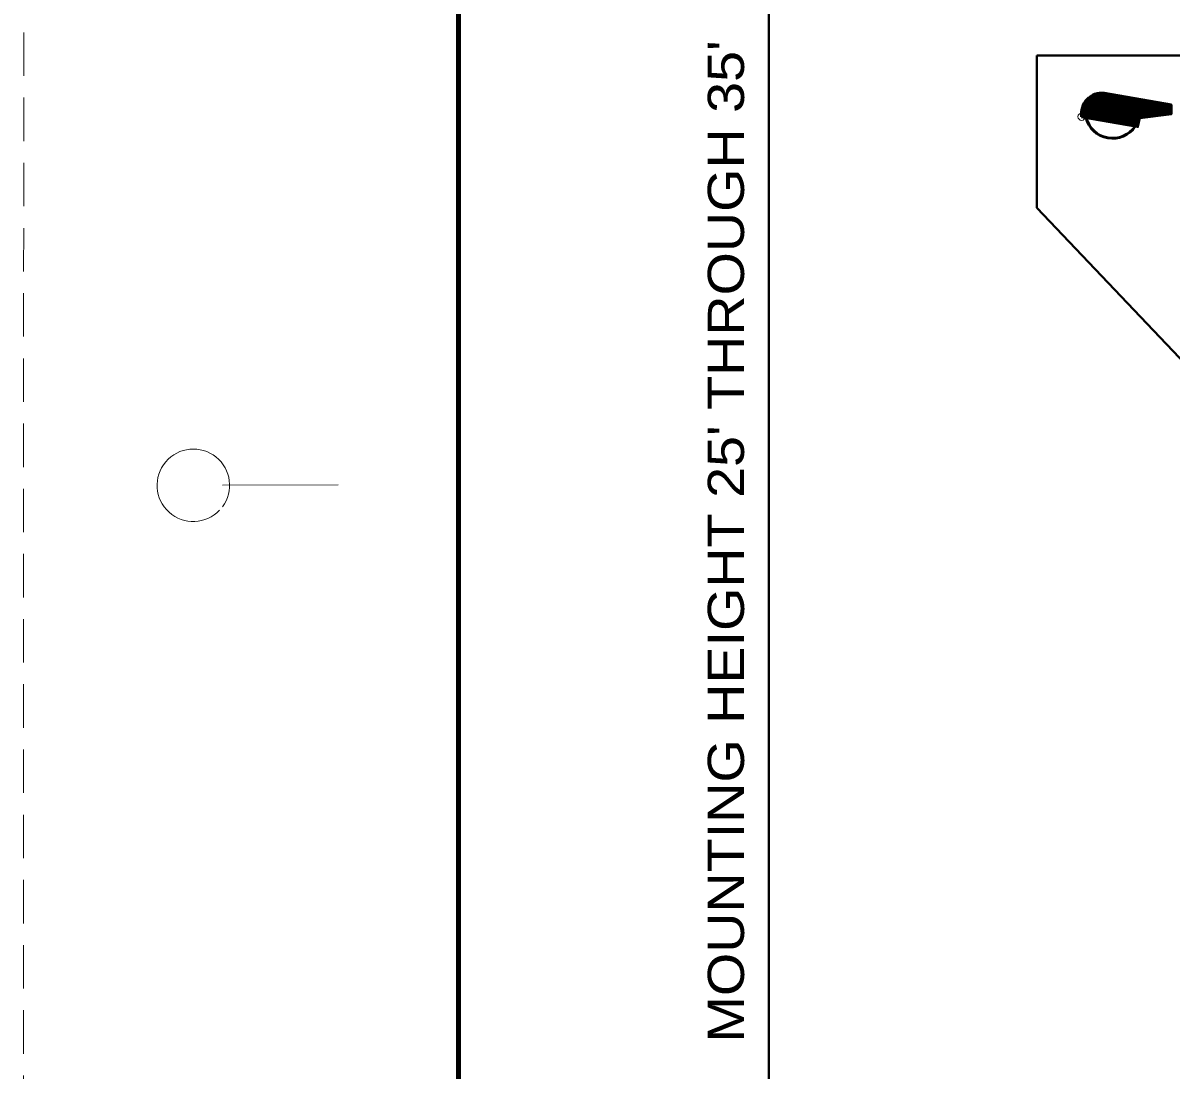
# Model space of a CAD drawing. Extents: x -1 to 679, y 1 to 441.
# Drawn here: x -0.7 to 78.6, y 301.7 to 374 of the extents above; entities that cross this region are included whole.
import ezdxf

# ---------------------------------------------------------------- set-up
doc = ezdxf.new("R2010")
doc.units = 0
doc.header["$PDMODE"] = 32
doc.header["$PDSIZE"] = 0.5
doc.linetypes.add('MEDIUM_DASHED', pattern=[4.5, 3, -1.5])
doc.layers.add('1', color=7, linetype='Continuous', lineweight=13)
doc.layers.add('61', color=7, linetype='Continuous', lineweight=35)

msp = doc.modelspace()

# ---------------------------------------------------------------- linework, layer by layer
at = {"layer": '1', "linetype": 'MEDIUM_DASHED'}
msp.add_line((-0.608, 440.866), (-0.668, 0.826), dxfattribs=at)
at = {"layer": '1', "lineweight": 40}
for p, q in [((50.801, 409.017), (50.801, 261.017)), ((69.301, 371.767), (69.301, 361.267)), ((126.301, 371.767), (69.301, 371.767)), ((69.301, 361.267), (87.801, 341.767))]:
    msp.add_line(p, q, dxfattribs=at)
at = {"layer": '1', "lineweight": 53}
for p, q in [((72.408, 368.076), (73.478, 369.147)), ((72.42, 368.133), (73.419, 369.132)), ((72.442, 368.199), (73.355, 369.112)), ((72.464, 368.265), (73.288, 369.09)), ((72.498, 368.343), (73.211, 369.056)), ((72.537, 368.427), (73.124, 369.013)), ((72.601, 368.535), (73.017, 368.951)), ((72.621, 368.246), (73.533, 369.158)), ((72.666, 368.246), (73.588, 369.169)), ((72.71, 368.246), (73.637, 369.173)), ((72.754, 368.246), (73.686, 369.178)), ((72.798, 368.246), (73.735, 369.183)), ((72.798, 368.776), (72.799, 368.777)), ((72.842, 368.246), (73.779, 369.183)), ((72.886, 368.246), (73.823, 369.182)), ((72.931, 368.246), (73.867, 369.182)), ((72.975, 368.246), (73.909, 369.18)), ((73.019, 368.246), (73.949, 369.176)), ((73.063, 368.246), (73.986, 369.169)), ((73.108, 368.246), (74.024, 369.162)), ((73.152, 368.246), (74.062, 369.156)), ((73.196, 368.246), (74.099, 369.149)), ((73.24, 368.246), (74.137, 369.142)), ((73.284, 368.246), (74.174, 369.136)), ((73.328, 368.246), (74.212, 369.129)), ((73.373, 368.246), (74.249, 369.123)), ((73.417, 368.246), (74.287, 369.116)), ((73.461, 368.246), (74.325, 369.109)), ((73.505, 368.246), (74.362, 369.103)), ((73.549, 368.246), (74.4, 369.096)), ((73.594, 368.246), (74.437, 369.09)), ((73.638, 368.246), (74.475, 369.083)), ((73.682, 368.246), (74.512, 369.076)), ((73.726, 368.246), (74.55, 369.07)), ((73.77, 368.246), (74.588, 369.063)), ((73.815, 368.246), (74.625, 369.056)), ((73.859, 368.246), (74.663, 369.05)), ((73.903, 368.246), (74.7, 369.043)), ((73.947, 368.246), (74.738, 369.036)), ((73.991, 368.246), (74.775, 369.03)), ((74.036, 368.246), (74.813, 369.023)), ((74.08, 368.246), (74.851, 369.017)), ((74.124, 368.246), (74.888, 369.01)), ((74.168, 368.246), (74.926, 369.003)), ((74.212, 368.246), (74.963, 368.997)), ((74.257, 368.246), (75.001, 368.99)), ((74.301, 368.246), (75.038, 368.983)), ((74.345, 368.246), (75.076, 368.977)), ((74.389, 368.246), (75.114, 368.97)), ((74.433, 368.246), (75.151, 368.964)), ((74.477, 368.246), (75.189, 368.957)), ((74.522, 368.246), (75.226, 368.95)), ((74.566, 368.246), (75.264, 368.944)), ((74.61, 368.246), (75.301, 368.937)), ((74.654, 368.246), (75.339, 368.93)), ((74.698, 368.246), (75.377, 368.924)), ((74.743, 368.246), (75.414, 368.917)), ((74.787, 368.246), (75.452, 368.911)), ((74.831, 368.246), (75.489, 368.904)), ((74.875, 368.246), (75.527, 368.897)), ((74.919, 368.246), (75.564, 368.891)), ((74.964, 368.246), (75.602, 368.884)), ((75.008, 368.246), (75.639, 368.878)), ((75.052, 368.246), (75.677, 368.871)), ((75.096, 368.246), (75.715, 368.864)), ((75.14, 368.246), (75.752, 368.858)), ((75.185, 368.246), (75.79, 368.851)), ((75.229, 368.246), (75.827, 368.844)), ((75.273, 368.246), (75.865, 368.838)), ((75.317, 368.246), (75.903, 368.831)), ((75.361, 368.246), (75.94, 368.825)), ((75.406, 368.246), (75.978, 368.818)), ((75.45, 368.246), (76.015, 368.811)), ((75.494, 368.246), (76.053, 368.805)), ((75.538, 368.246), (76.09, 368.798)), ((75.582, 368.246), (76.128, 368.791)), ((75.627, 368.246), (76.166, 368.785)), ((75.671, 368.246), (76.203, 368.778)), ((75.715, 368.246), (76.241, 368.772)), ((75.759, 368.246), (76.278, 368.765)), ((75.803, 368.246), (76.316, 368.758)), ((75.847, 368.246), (76.353, 368.752)), ((75.892, 368.246), (76.391, 368.745)), ((75.936, 368.246), (76.428, 368.738)), ((75.98, 368.246), (76.466, 368.732)), ((76.024, 368.246), (76.504, 368.725)), ((76.069, 368.246), (76.541, 368.719)), ((76.113, 368.246), (76.579, 368.712)), ((76.157, 368.246), (76.616, 368.705)), ((76.201, 368.246), (76.654, 368.699)), ((76.245, 368.246), (76.691, 368.692)), ((76.29, 368.246), (76.729, 368.685)), ((76.334, 368.246), (76.767, 368.679)), ((76.378, 368.246), (76.804, 368.672)), ((76.422, 368.246), (76.842, 368.666)), ((76.466, 368.246), (76.879, 368.659)), ((76.51, 368.246), (76.917, 368.652)), ((76.555, 368.246), (76.954, 368.646)), ((76.599, 368.246), (76.992, 368.639)), ((76.643, 368.246), (77.03, 368.632)), ((76.687, 368.246), (77.067, 368.626)), ((76.731, 368.246), (77.105, 368.619)), ((76.776, 368.246), (77.142, 368.613)), ((76.82, 368.246), (77.18, 368.606)), ((76.864, 368.246), (77.217, 368.599)), ((76.908, 368.246), (77.255, 368.593)), ((76.952, 368.246), (77.293, 368.586)), ((76.997, 368.246), (77.33, 368.579)), ((77.041, 368.246), (77.368, 368.573)), ((77.085, 368.246), (77.405, 368.566)), ((77.129, 368.246), (77.443, 368.56)), ((77.173, 368.246), (77.48, 368.553)), ((77.218, 368.246), (77.518, 368.546)), ((77.262, 368.246), (77.556, 368.54)), ((77.306, 368.246), (77.593, 368.533)), ((77.35, 368.246), (77.631, 368.526)), ((77.394, 368.246), (77.668, 368.52)), ((77.439, 368.246), (77.706, 368.513)), ((77.483, 368.246), (77.743, 368.506)), ((77.527, 368.246), (77.781, 368.5)), ((77.571, 368.246), (77.819, 368.493)), ((77.615, 368.246), (77.856, 368.487)), ((77.659, 368.246), (77.894, 368.48)), ((77.704, 368.246), (77.931, 368.473)), ((77.748, 368.246), (77.969, 368.467)), ((77.792, 368.246), (78.006, 368.46)), ((77.836, 368.246), (78.044, 368.453)), ((77.88, 368.246), (78.082, 368.447)), ((77.925, 368.246), (78.119, 368.44)), ((77.969, 368.246), (78.157, 368.434)), ((78.013, 368.246), (78.194, 368.427)), ((78.057, 368.246), (78.232, 368.42)), ((78.102, 368.246), (78.269, 368.414)), ((78.146, 368.246), (78.307, 368.407)), ((78.19, 368.246), (78.344, 368.401)), ((72.371, 367.775), (72.764, 368.168)), ((72.371, 367.73), (72.808, 368.168)), ((72.371, 367.686), (72.853, 368.168)), ((72.372, 367.819), (72.72, 368.168)), ((72.374, 367.866), (72.676, 368.168)), ((72.375, 367.646), (72.897, 368.168)), ((72.379, 367.606), (72.941, 368.168)), ((72.38, 367.916), (72.632, 368.168)), ((72.383, 367.565), (72.985, 368.168)), ((72.386, 367.966), (72.612, 368.192)), ((72.395, 368.019), (72.612, 368.237)), ((72.406, 367.544), (73.029, 368.168)), ((72.443, 367.537), (73.074, 368.168)), ((72.481, 367.531), (73.118, 368.168)), ((72.518, 367.524), (73.162, 368.168)), ((72.556, 367.517), (73.206, 368.168)), ((72.593, 367.511), (73.25, 368.168)), ((72.631, 367.504), (73.294, 368.168)), ((72.668, 367.498), (73.339, 368.168)), ((72.706, 367.491), (73.383, 368.168)), ((72.744, 367.484), (73.427, 368.168)), ((72.781, 367.478), (73.471, 368.168)), ((72.819, 367.471), (73.516, 368.168)), ((72.856, 367.464), (73.56, 368.168)), ((72.894, 367.458), (73.604, 368.168)), ((72.931, 367.451), (73.648, 368.168)), ((72.969, 367.444), (73.692, 368.168)), ((73.007, 367.438), (73.736, 368.168)), ((73.044, 367.431), (73.781, 368.168)), ((73.082, 367.425), (73.825, 368.168)), ((73.119, 367.418), (73.869, 368.168)), ((73.157, 367.411), (73.913, 368.168)), ((73.194, 367.405), (73.957, 368.168)), ((73.232, 367.398), (74.002, 368.168)), ((73.27, 367.391), (74.046, 368.168)), ((73.307, 367.385), (74.09, 368.168)), ((73.345, 367.378), (74.134, 368.168)), ((73.382, 367.372), (74.178, 368.168)), ((73.42, 367.365), (74.223, 368.168)), ((73.457, 367.358), (74.267, 368.168)), ((73.495, 367.352), (74.311, 368.168)), ((73.533, 367.345), (74.355, 368.168)), ((73.57, 367.339), (74.399, 368.168)), ((73.608, 367.332), (74.444, 368.168)), ((73.645, 367.325), (74.488, 368.168)), ((73.683, 367.319), (74.532, 368.168)), ((73.72, 367.312), (74.576, 368.168)), ((73.758, 367.305), (74.62, 368.168)), ((73.796, 367.299), (74.665, 368.168)), ((73.833, 367.292), (74.709, 368.168)), ((73.871, 367.286), (74.753, 368.168)), ((73.908, 367.279), (74.797, 368.168)), ((73.946, 367.272), (74.841, 368.168)), ((73.983, 367.266), (74.886, 368.168)), ((74.021, 367.259), (74.93, 368.168)), ((74.059, 367.252), (74.974, 368.168)), ((74.096, 367.246), (75.018, 368.168)), ((74.134, 367.239), (75.062, 368.168)), ((74.171, 367.233), (75.106, 368.168)), ((74.209, 367.226), (75.151, 368.168)), ((74.246, 367.219), (75.195, 368.168)), ((74.284, 367.213), (75.239, 368.168)), ((74.322, 367.206), (75.283, 368.168)), ((74.359, 367.199), (75.328, 368.168)), ((74.397, 367.193), (75.372, 368.168)), ((74.434, 367.186), (75.416, 368.168)), ((74.472, 367.179), (75.46, 368.168)), ((74.509, 367.173), (75.504, 368.168)), ((74.547, 367.166), (75.549, 368.168)), ((74.584, 367.16), (75.593, 368.168)), ((74.622, 367.153), (75.637, 368.168)), ((74.66, 367.146), (75.681, 368.168)), ((74.697, 367.14), (75.725, 368.168)), ((74.735, 367.133), (75.769, 368.168)), ((74.772, 367.126), (75.814, 368.168)), ((74.81, 367.12), (75.858, 368.168)), ((74.847, 367.113), (75.902, 368.168)), ((74.885, 367.107), (75.946, 368.168)), ((74.923, 367.1), (75.99, 368.168)), ((74.96, 367.093), (76.035, 368.168)), ((74.998, 367.087), (76.079, 368.168)), ((75.035, 367.08), (76.123, 368.168)), ((75.073, 367.073), (76.167, 368.168)), ((75.11, 367.067), (76.211, 368.168)), ((75.148, 367.06), (76.256, 368.168)), ((75.186, 367.054), (76.3, 368.168)), ((75.223, 367.047), (76.344, 368.168)), ((75.261, 367.04), (76.388, 368.168)), ((75.298, 367.034), (76.432, 368.168)), ((75.336, 367.027), (76.477, 368.168)), ((75.373, 367.02), (76.521, 368.168)), ((75.411, 367.014), (76.565, 368.168)), ((75.449, 367.007), (76.609, 368.168)), ((75.486, 367.001), (76.653, 368.168)), ((75.524, 366.994), (76.697, 368.168)), ((75.561, 366.987), (76.742, 368.168)), ((75.599, 366.981), (76.786, 368.168)), ((75.636, 366.974), (76.83, 368.168)), ((75.674, 366.967), (76.874, 368.168)), ((75.712, 366.961), (76.918, 368.168)), ((75.749, 366.954), (76.963, 368.168)), ((75.787, 366.948), (77.007, 368.168)), ((75.824, 366.941), (77.051, 368.168)), ((76.401, 367.473), (77.095, 368.168)), ((76.451, 367.479), (77.139, 368.168)), ((76.501, 367.486), (77.184, 368.168)), ((76.552, 367.492), (77.228, 368.168)), ((76.602, 367.498), (77.272, 368.168)), ((76.653, 367.504), (77.316, 368.168)), ((76.703, 367.51), (77.36, 368.168)), ((76.754, 367.517), (77.405, 368.168)), ((76.804, 367.523), (77.449, 368.168)), ((76.854, 367.529), (77.493, 368.168)), ((76.905, 367.535), (77.537, 368.168)), ((76.955, 367.541), (77.581, 368.168)), ((77.005, 367.548), (77.626, 368.168)), ((77.056, 367.554), (77.67, 368.168)), ((77.106, 367.56), (77.714, 368.168)), ((77.156, 367.566), (77.758, 368.168)), ((77.207, 367.572), (77.802, 368.168)), ((77.257, 367.578), (77.847, 368.168)), ((77.308, 367.585), (77.891, 368.168)), ((77.358, 367.591), (77.935, 368.168)), ((77.408, 367.597), (77.979, 368.168)), ((77.459, 367.603), (78.023, 368.168)), ((77.509, 367.609), (78.067, 368.168)), ((77.559, 367.615), (78.112, 368.168)), ((77.61, 367.622), (78.156, 368.168)), ((77.66, 367.628), (78.2, 368.168)), ((77.711, 367.634), (78.244, 368.168)), ((77.761, 367.64), (78.288, 368.168)), ((77.811, 367.646), (78.333, 368.168)), ((77.862, 367.653), (78.377, 368.168)), ((77.912, 367.659), (78.557, 368.304)), ((77.962, 367.665), (78.557, 368.26)), ((78.013, 367.671), (78.557, 368.216)), ((78.063, 367.677), (78.557, 368.171)), ((78.114, 367.683), (78.557, 368.127)), ((78.164, 367.69), (78.557, 368.083)), ((78.214, 367.696), (78.557, 368.039)), ((78.234, 368.246), (78.382, 368.394)), ((78.265, 367.702), (78.557, 367.995)), ((78.278, 368.246), (78.42, 368.387)), ((78.315, 367.708), (78.557, 367.95)), ((78.322, 368.246), (78.457, 368.381)), ((78.366, 367.714), (78.557, 367.906)), ((78.367, 368.246), (78.495, 368.374)), ((78.401, 368.236), (78.532, 368.368)), ((78.401, 368.192), (78.557, 368.348)), ((78.416, 367.721), (78.557, 367.862)), ((78.466, 367.727), (78.557, 367.818)), ((78.517, 367.733), (78.557, 367.774)), ((75.862, 366.934), (76.382, 367.455)), ((75.899, 366.928), (76.369, 367.397)), ((75.937, 366.921), (76.356, 367.34)), ((75.975, 366.914), (76.343, 367.282)), ((76.012, 366.908), (76.329, 367.225)), ((76.05, 366.901), (76.316, 367.167)), ((76.087, 366.895), (76.303, 367.11)), ((76.125, 366.888), (76.289, 367.053)), ((76.162, 366.881), (76.276, 366.995)), ((76.2, 366.875), (76.263, 366.938)), ((76.237, 366.868), (76.25, 366.88))]:
    msp.add_line(p, q, dxfattribs=at)
msp.add_lwpolyline([(73.941, 369.177), (78.557, 368.363), (78.557, 367.738), (76.386, 367.471), (76.246, 366.866), (72.385, 367.548)], dxfattribs=at)
at = {"layer": '1'}
msp.add_lwpolyline([(72.612, 368.246), (78.401, 368.246), (78.401, 368.168), (72.612, 368.168)], close=True, dxfattribs=at)
at = {"layer": '1', "lineweight": 53}
for centre, radius, start, end in [((73.798, 367.756), 1.429, 84.23953, 188.38162), ((74.526, 367.949), 1.889, 193.94762, 326.05059)]:
    msp.add_arc(centre, radius, start, end, dxfattribs=at)
at = {"layer": '1'}
msp.add_point((72.385, 367.548), dxfattribs=at)
at = {"layer": '61', "lineweight": 13}
msp.add_line((13.112, 342.106), (21.092, 342.126), dxfattribs=at)
at = {"layer": '61', "lineweight": 158}
msp.add_lwpolyline([(668.432, 430.866), (29.392, 430.866), (29.392, 10.846)], dxfattribs=at)
at = {"layer": '61', "lineweight": 13}
msp.add_arc((11.09, 342.107), 2.5, 323.13009, 316.23216, dxfattribs=at)

# ---------------------------------------------------------------- texts
at = {"layer": '1', "width": 1.15}
msp.add_text("MOUNTING HEIGHT 25' THROUGH 35'", height=2.5, rotation=90, dxfattribs=at).set_placement((49.09, 303.642))

doc.saveas('drawing.dxf')
